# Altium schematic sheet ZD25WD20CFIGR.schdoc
size 127 x 101 mm
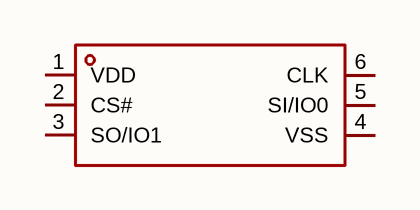
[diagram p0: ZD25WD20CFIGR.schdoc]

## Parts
U?  zd25wd20cfigr  [USON-6_L1.2-W0.7_ZD25WD20CFIGR]  (value not drawn)

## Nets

Not connected (* = marked no-connect by the designer): U? 1(VDD) 2(CS#) 3(SO/IO1) 4(VSS) 5(SI/IO0) 6(CLK)

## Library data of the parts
U? = zd25wd20cfigr: 接口类型:SPI;存储容量:2Mbit;时钟频率(fc):104MHz;; Manufacturer: Zetta(澜智); AddInBom: yes; Interface: SPI; Memory Size: 2Mbit; Clock Frequency: 104MHz; Voltage - Supply: 1.65V~3.6V; Standby Supply Current: 0.5uA; Program / Erase Cycles: 100000次; Page Programming Time (Tpp): 2ms; Block Erase Time(tBE): 13ms; Data Retention - TDR (Year): 20年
